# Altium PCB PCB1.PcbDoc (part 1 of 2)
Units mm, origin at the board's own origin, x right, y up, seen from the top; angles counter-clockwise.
Board outline 140.21 x 210.44 mm, 4 copper layers (Top Layer, Layer 1, Layer 2, Bottom Layer), stack 0.603 mm thick; 99 components, 45 nets, 371 pads, 603 vias.
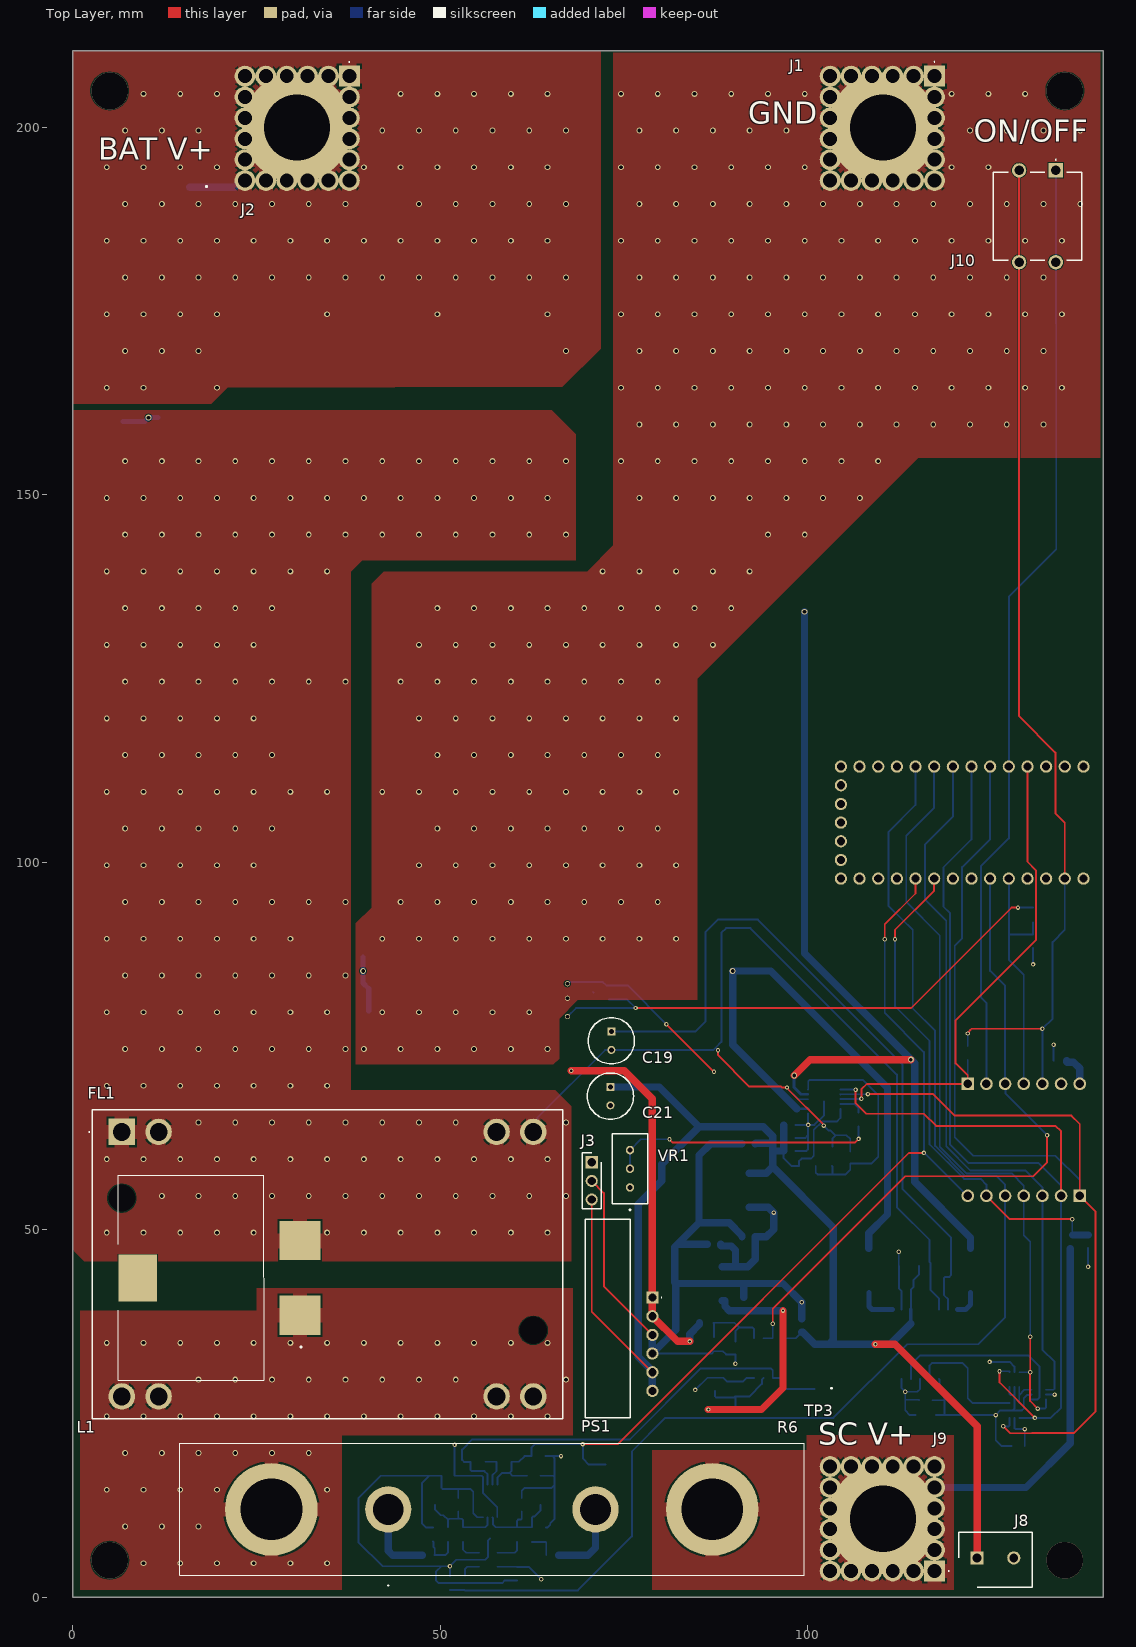
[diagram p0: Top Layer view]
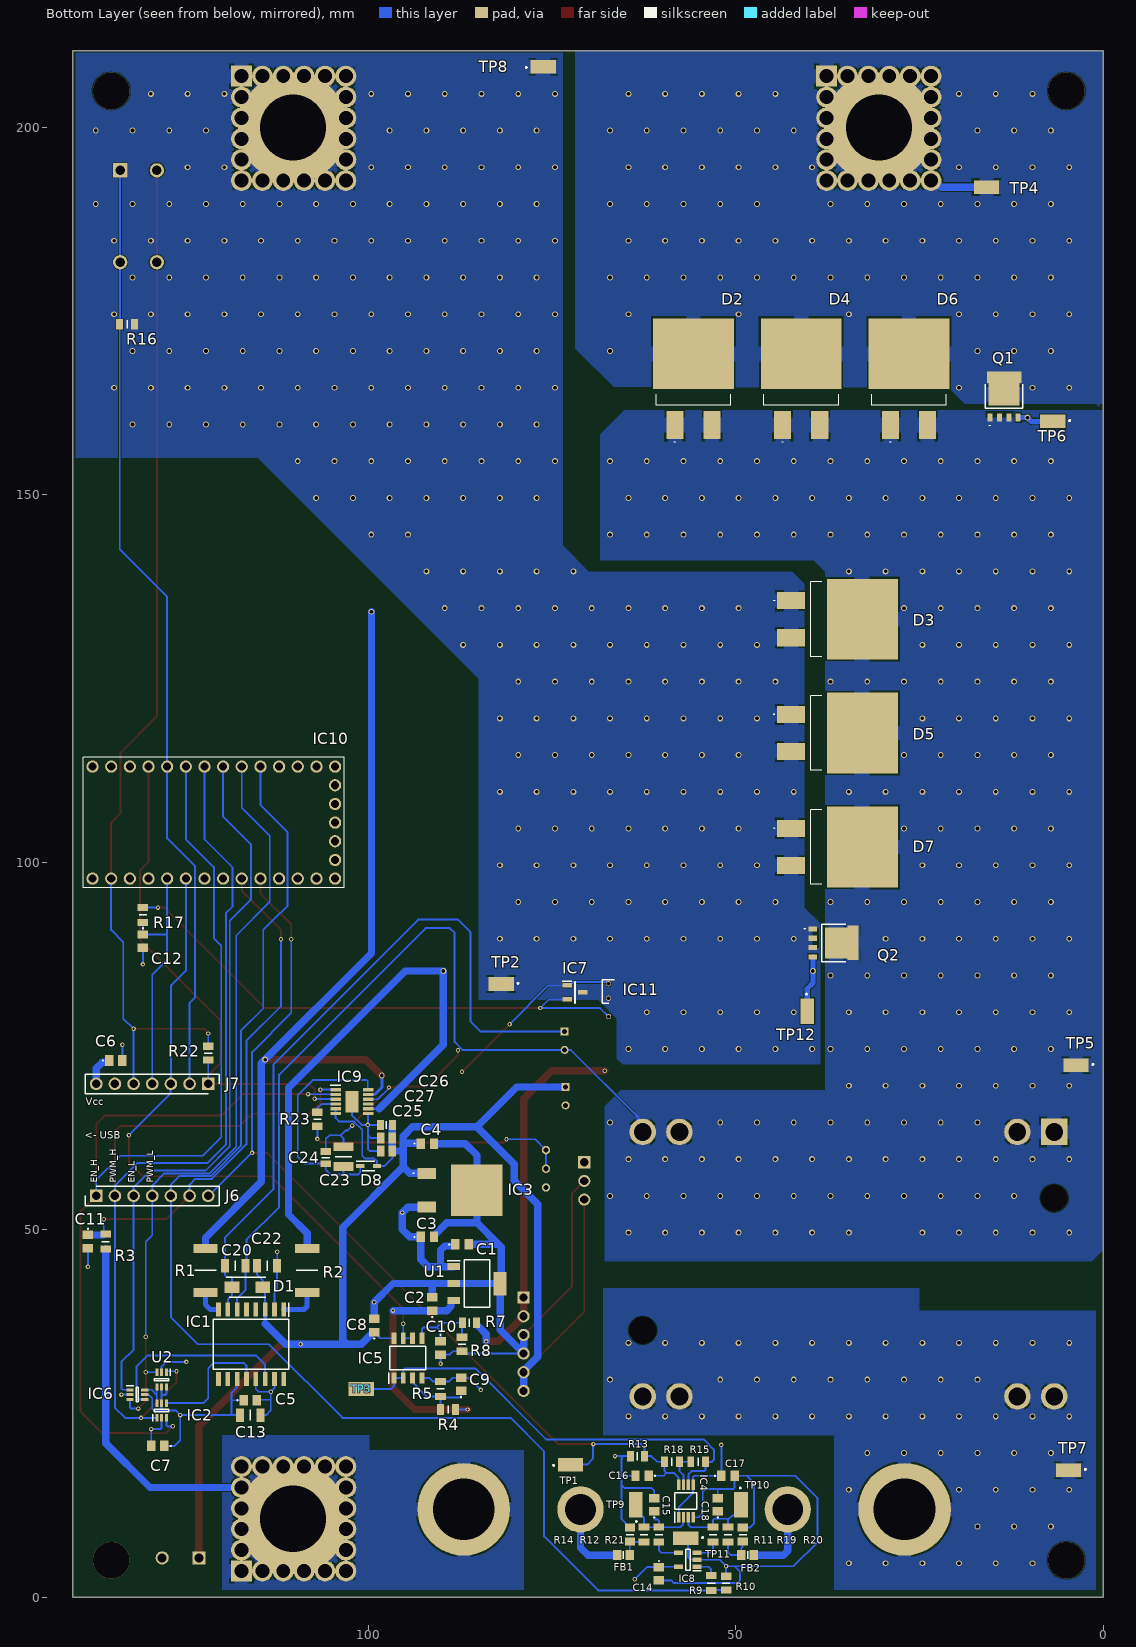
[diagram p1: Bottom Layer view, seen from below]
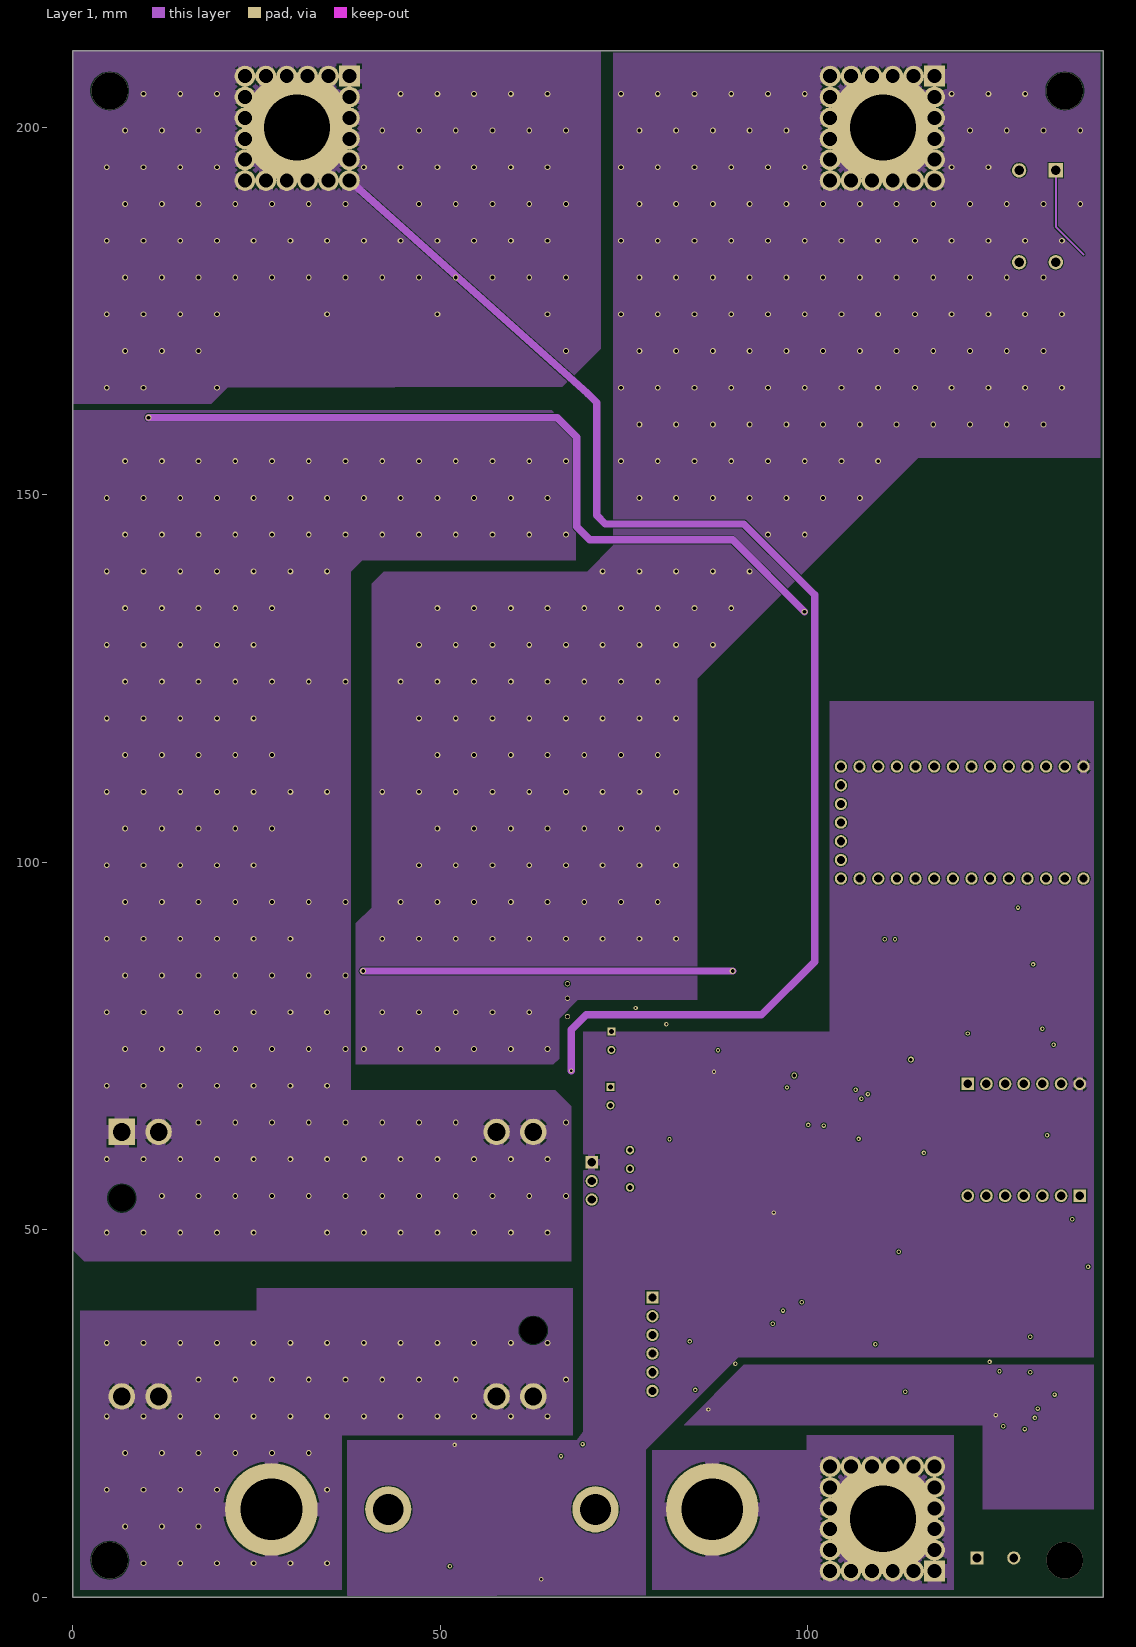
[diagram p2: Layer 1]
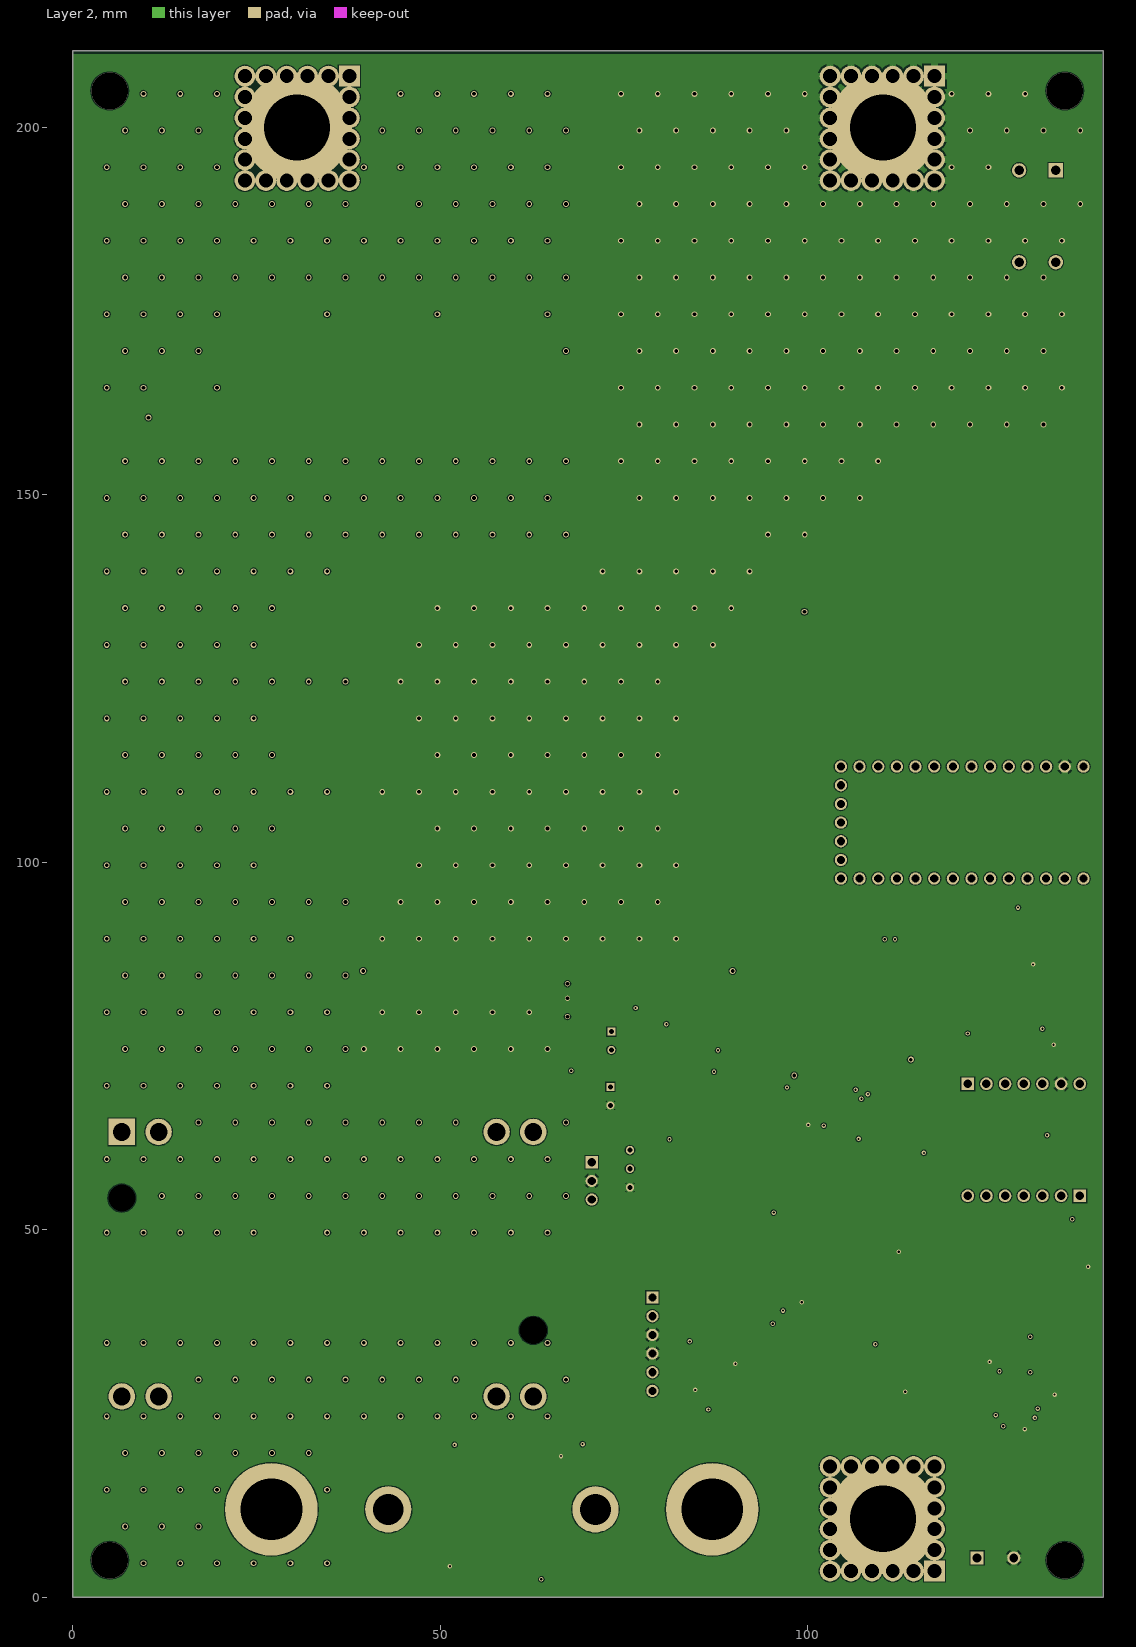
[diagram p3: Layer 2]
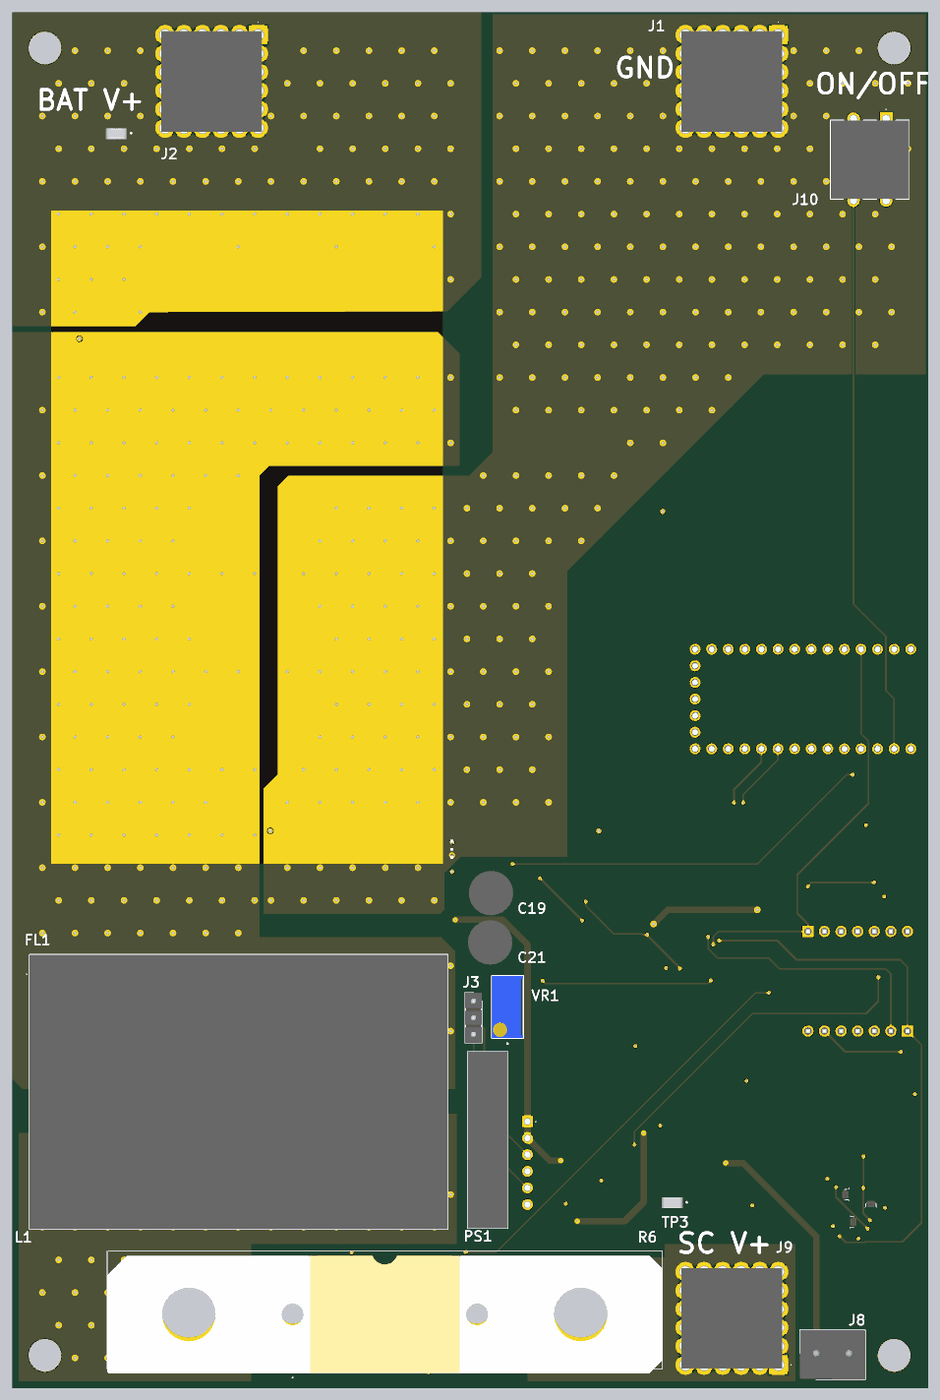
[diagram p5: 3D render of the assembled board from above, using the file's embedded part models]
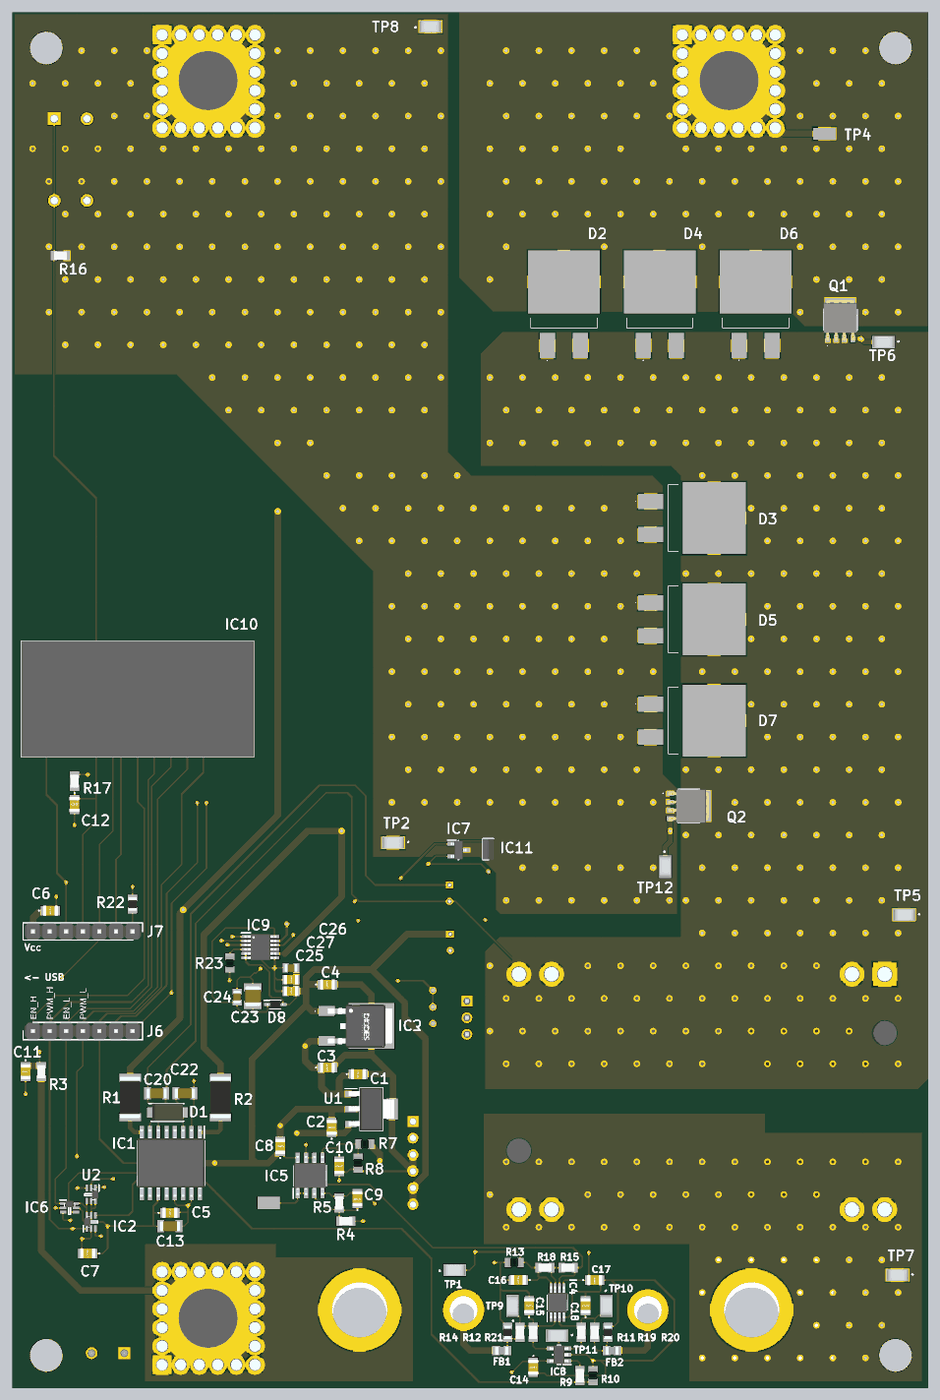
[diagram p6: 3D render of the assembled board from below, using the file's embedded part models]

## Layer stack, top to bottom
Top Solder: solder mask 0.0102, Solder Resist, Dk 3.5
Top Layer: signal copper 0.0356
Dielectric 2: prepreg 0.0711, PP-006, Dk 4.1
Layer 1: signal copper 0.035
Dielectric 1: dielectric 0.32, FR-4, Dk 4.8
Layer 2: signal copper 0.035
Dielectric 3: prepreg 0.0711, PP-006, Dk 4.1
Bottom Layer: signal copper 0.0356
Bottom Solder: solder mask 0.0102, Solder Resist, Dk 3.5

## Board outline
0,0 140.208,0 140.208,210.439 0,210.439

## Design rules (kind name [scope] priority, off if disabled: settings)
Clearance [All] p1: gap=0.127 ignorepadtopadclearanceinfootprint=FALSE
PolygonConnect PolygonConnect_5 [All vs IsNamedPolygon('GND') Or IsNamedPolygon('GND') Or IsNamedPolygon('GND') Or IsNamedPolygon('Top Layer-NetFL1_A2') Or IsNamedPolygon('Top Layer-SUPERCAPACITOR_V+') Or IsNamedPolygon('GND') Or IsNamedPolygon('GND') Or IsNamedPolygon('GND') Or IsNamedPolygon('Top Layer-NetFL1_A2') Or IsNamedPolygon('Top Layer-SUPERCAPACITOR_V+') Or IsNamedPolygon('GND') Or IsNamedPolygon('GND') Or IsNamedPolygon('Top Layer-NetFL1_A2') Or IsNamedPolygon('Top Layer-SUPERCAPACITOR_V+') Or IsNamedPolygon('GND') Or IsNamedPolygon('GND') Or IsNamedPolygon('GND') Or IsNamedPolygon('GND') Or IsNamedPolygon('Top Layer-NetFL1_A2') Or IsNamedPolygon('Top Layer-SUPERCAPACITOR_V+')] p1: thpad.connectstyle=Relief thpad.reliefconductorwidth=2 thpad.reliefentries=4 thpad.polygonreliefangle="90 Angle" thpad.airgapwidth=0.254 smdpad.connectstyle=Relief smdpad.reliefconductorwidth=2 smdpad.reliefentries=4 smdpad.polygonreliefangle="90 Angle" smdpad.airgapwidth=0.254 via.connectstyle=Direct via.reliefconductorwidth=0.254 via.reliefentries=4 via.polygonreliefangle="90 Angle" via.airgapwidth=0.254
PolygonConnect PolygonConnect_4 [All vs IsNamedPolygon('GND') Or IsNamedPolygon('GND') Or IsNamedPolygon('GND') Or IsNamedPolygon('Top Layer-NetFL1_A2') Or IsNamedPolygon('Top Layer-SUPERCAPACITOR_V+') Or IsNamedPolygon('GND') Or IsNamedPolygon('GND') Or IsNamedPolygon('GND') Or IsNamedPolygon('Layer 1-VCC_3V') Or IsNamedPolygon('Layer 1-VCC_5V') Or IsNamedPolygon('Top Layer-NetFL1_A2') Or IsNamedPolygon('Top Layer-SUPERCAPACITOR_V+') Or IsNamedPolygon('GND') Or IsNamedPolygon('GND') Or IsNamedPolygon('Layer 2-GND') Or IsNamedPolygon('Top Layer-NetFL1_A2') Or IsNamedPolygon('Top Layer-SUPERCAPACITOR_V+') Or IsNamedPolygon('GND') Or IsNamedPolygon('GND') Or IsNamedPolygon('GND') Or IsNamedPolygon('GND') Or IsNamedPolygon('Top Layer-NetFL1_A2') Or IsNamedPolygon('Top Layer-SUPERCAPACITOR_V+')] p2: thpad.connectstyle=Relief thpad.reliefconductorwidth=1 thpad.reliefentries=4 thpad.polygonreliefangle="90 Angle" thpad.airgapwidth=0.254 smdpad.connectstyle=Relief smdpad.reliefconductorwidth=1 smdpad.reliefentries=4 smdpad.polygonreliefangle="90 Angle" smdpad.airgapwidth=0.254 via.connectstyle=Direct via.reliefconductorwidth=0.254 via.reliefentries=4 via.polygonreliefangle="90 Angle" via.airgapwidth=0.254
PolygonConnect PolygonConnect_3 [All vs IsNamedPolygon('GND') Or IsNamedPolygon('GND') Or IsNamedPolygon('GND') Or IsNamedPolygon('Top Layer-NetFL1_A2') Or IsNamedPolygon('Top Layer-SUPERCAPACITOR_V+') Or IsNamedPolygon('GND') Or IsNamedPolygon('GND') Or IsNamedPolygon('GND') Or IsNamedPolygon('Layer 1-VCC_3V') Or IsNamedPolygon('Layer 1-VCC_5V') Or IsNamedPolygon('Top Layer-NetFL1_A2') Or IsNamedPolygon('Top Layer-SUPERCAPACITOR_V+') Or IsNamedPolygon('GND') Or IsNamedPolygon('GND') Or IsNamedPolygon('Layer 2-GND') Or IsNamedPolygon('Top Layer-NetFL1_A2') Or IsNamedPolygon('Top Layer-SUPERCAPACITOR_V+') Or IsNamedPolygon('GND') Or IsNamedPolygon('GND') Or IsNamedPolygon('GND') Or IsNamedPolygon('GND') Or IsNamedPolygon('Top Layer-NetFL1_A2') Or IsNamedPolygon('Top Layer-SUPERCAPACITOR_V+')] p3: thpad.connectstyle=Relief thpad.reliefconductorwidth=0.5 thpad.reliefentries=4 thpad.polygonreliefangle="90 Angle" thpad.airgapwidth=0.254 smdpad.connectstyle=Relief smdpad.reliefconductorwidth=0.254 smdpad.reliefentries=4 smdpad.polygonreliefangle="90 Angle" smdpad.airgapwidth=0.254 via.connectstyle=Relief via.reliefconductorwidth=0.254 via.reliefentries=4 via.polygonreliefangle="90 Angle" via.airgapwidth=0.254
PolygonConnect PolygonConnect_2 [All vs IsNamedPolygon('GND') Or IsNamedPolygon('GND') Or IsNamedPolygon('GND') Or IsNamedPolygon('Top Layer-NetFL1_A2') Or IsNamedPolygon('Top Layer-SUPERCAPACITOR_V+') Or IsNamedPolygon('GND') Or IsNamedPolygon('GND') Or IsNamedPolygon('GND') Or IsNamedPolygon('Layer 1-VCC_3V') Or IsNamedPolygon('Layer 1-VCC_5V') Or IsNamedPolygon('Top Layer-NetFL1_A2') Or IsNamedPolygon('Top Layer-SUPERCAPACITOR_V+') Or IsNamedPolygon('GND') Or IsNamedPolygon('GND') Or IsNamedPolygon('Layer 2-GND') Or IsNamedPolygon('Top Layer-NetFL1_A2') Or IsNamedPolygon('Top Layer-SUPERCAPACITOR_V+') Or IsNamedPolygon('GND') Or IsNamedPolygon('GND') Or IsNamedPolygon('GND') Or IsNamedPolygon('GND') Or IsNamedPolygon('Top Layer-NetFL1_A2') Or IsNamedPolygon('Top Layer-SUPERCAPACITOR_V+')] p4: thpad.connectstyle=Relief thpad.reliefconductorwidth=0.254 thpad.reliefentries=4 thpad.polygonreliefangle="90 Angle" thpad.airgapwidth=0.254 smdpad.connectstyle=Relief smdpad.reliefconductorwidth=0.254 smdpad.reliefentries=4 smdpad.polygonreliefangle="90 Angle" smdpad.airgapwidth=0.254 via.connectstyle=Direct via.reliefconductorwidth=0.254 via.reliefentries=4 via.polygonreliefangle="90 Angle" via.airgapwidth=0.254
PolygonConnect HESS2 [All vs IsNamedPolygon('GND') Or IsNamedPolygon('Top Layer-NetFL1_A2') Or IsNamedPolygon('Top Layer-SUPERCAPACITOR_V+') Or IsNamedPolygon('Top Layer-SUPERCAPACITOR_V+') Or IsNamedPolygon('GND') Or IsNamedPolygon('Top Layer-SUPERCAPACITOR_V+') Or IsNamedPolygon('GND') Or IsNamedPolygon('GND') Or IsNamedPolygon('GND') Or IsNamedPolygon('GND') Or IsNamedPolygon('Top Layer-SUPERCAPACITOR_V+')] p5: thpad.connectstyle=Relief thpad.reliefconductorwidth=1 thpad.reliefentries=4 thpad.polygonreliefangle="90 Angle" thpad.airgapwidth=0.254 smdpad.connectstyle=Relief smdpad.reliefconductorwidth=1 smdpad.reliefentries=4 smdpad.polygonreliefangle="90 Angle" smdpad.airgapwidth=0.254 via.connectstyle=Relief via.reliefconductorwidth=0.254 via.reliefentries=4 via.polygonreliefangle="90 Angle" via.airgapwidth=0.254
PolygonConnect PolygonConnect_1 [All vs IsNamedPolygon('GND')] p6: thpad.connectstyle=Relief thpad.reliefconductorwidth=1 thpad.reliefentries=4 thpad.polygonreliefangle="90 Angle" thpad.airgapwidth=0.254 smdpad.connectstyle=Relief smdpad.reliefconductorwidth=1 smdpad.reliefentries=4 smdpad.polygonreliefangle="90 Angle" smdpad.airgapwidth=0.254 via.connectstyle=Relief via.reliefconductorwidth=0.254 via.reliefentries=4 via.polygonreliefangle="90 Angle" via.airgapwidth=0.254
PolygonConnect HESS [All vs IsNamedPolygon('GND')] p7: thpad.connectstyle=Relief thpad.reliefconductorwidth=1 thpad.reliefentries=4 thpad.polygonreliefangle="90 Angle" thpad.airgapwidth=0.254 smdpad.connectstyle=Relief smdpad.reliefconductorwidth=0.254 smdpad.reliefentries=4 smdpad.polygonreliefangle="90 Angle" smdpad.airgapwidth=0.254 via.connectstyle=Relief via.reliefconductorwidth=0.254 via.reliefentries=4 via.polygonreliefangle="90 Angle" via.airgapwidth=0.254
PolygonConnect [All] p8: connectstyle=Relief reliefconductorwidth=0.254 reliefentries=4 polygonreliefangle="90 Angle" airgapwidth=0.254
RoutingVias [All] p1: holewidth=0.711 width=1.27 viastyle="Through Hole" minholewidth=0.711 minwidth=1.27 maxholewidth=0.711 maxwidth=1.27
SolderMaskExpansion [All] p1: expansion=0.102 istentingtop=FALSE
SupplyNets "Schematic Supply Nets" [InNet('GND')] p1: voltage=0.000
Width [All] p1: maxlimit=2.54 minlimit=0.254 preferedwidth=1
30 further rules are at their usual default settings.

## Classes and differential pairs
component class DRIVER_2: C23 C24 C25 C26 C27 D8 IC9 R22 R23 VR1
component class CURRENT_SENSE: C14 C15 C16 C17 C18 FB1 FB2 IC4 IC8 R9 R10 R11 R12 R13 R14 R15 R18 R19 R20 R21 TP1 TP3 TP9 TP10 TP11
component class MOSFET_AND_INTRUMENTAL_AMPLIFIERS: C8 C9 C10 D2 D3 D4 D5 D6 D7 FL1 IC5 J1 J2 J9 L1 Q1 Q2 R4 R5 R6 R7 R8 TP2 TP4 TP5 TP6 TP7 TP8 TP12
component class MCU: C11 C12 IC7 IC10 IC11 J6 J7 J10 R3 R16 R17
component class DRIVER_ADN_REGULATORS: C1 C2 C3 C4 C5 C6 C7 C13 C19 C20 C21 C22 D1 IC1 IC2 IC3 IC6 J3 J8 PS1 R1 R2 U1 U2

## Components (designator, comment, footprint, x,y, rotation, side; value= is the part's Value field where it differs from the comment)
C1 "0.33 uF" C0805 87.249,48.006 r180 bottom
C2 "0.1 uF" C0805 91.313,39.878 r90 bottom
C3 "0.1 uF" C0805 91.962,49.022 r180 bottom
C4 "0.33 uF" C0805 91.962,61.722 r180 bottom
C5 "0.1 uF" C0805 116.078,26.797 r180 bottom
C6 "0.1 uF" C0805 134.366,73.025 r180 bottom
C7 "0.1 uF" C0805 128.651,20.574 r0 bottom
C8 "0.1 uF" C0805 99.187,36.957 r90 bottom
C9 "0.1 uF" C0805 87.376,28.956 r90 bottom
C10 "0.1 uF" C0805 90.17,33.909 r270 bottom
C11 "0.1 uF" C0805 138.176,48.387 r270 bottom
C12 "0.1 uF" C0805 130.683,89.281 r270 bottom
C13 "10 uF" CAPC3216X180N 116.078,24.765 r180 bottom
C14 "0.1 uF" C0805 60.452,3.175 r270 bottom
C15 "0.1 uF" C0805 61.087,12.573 r90 bottom
C16 "0.1 uF" C0805 62.738,16.51 r0 bottom
C17 "0.1 uF" C0805 51.054,16.51 r180 bottom
C18 "0.1 uF" C0805 52.451,12.573 r90 bottom
C19 "100 uF" CAPPRD250W52D630H1250 73.279,76.962 r270 top
C20 "10 uF" CAPC3216X180N 118.11,45.085 r180 bottom
C21 "100 uF" CAPPRD250W52D630H1250 73.152,69.429 r270 top
C22 "10 uF" CAPC3216X180N 113.792,45.085 r180 bottom
C23 "22 uF" CAPC3225X270N 103.378,59.944 r270 bottom
C24 "1 uF" CAPC2012X135N 105.791,59.817 r270 bottom
C25 "0.1 uF" CAPC2012X88N 97.536,60.706 r0 bottom
C26 "1 uF" CAPC2012X135N 97.536,64.262 r0 bottom
C27 "0.22 uF" CAPC2012X140N 97.536,62.484 r0 bottom
D1 "SK34SMA-3G" DIOM5027X240N 116.459,42.164 r180 bottom
D2 "VS-42CTQ030S-M3" VS42CTQ030SM3 55.753,163.195 r180 bottom
D3 "VS-42CTQ030S-M3" VS42CTQ030SM3 38.791,133.096 r270 bottom
D4 "VS-42CTQ030S-M3" VS42CTQ030SM3 41.084,163.195 r180 bottom
D5 "VS-42CTQ030S-M3" VS42CTQ030SM3 38.791,117.602 r270 bottom
D6 "VS-42CTQ030S-M3" VS42CTQ030SM3 26.416,163.195 r180 bottom
D7 "VS-42CTQ030S-M3" VS42CTQ030SM3 38.791,102.108 r270 bottom
D8 "PMEG2020AEA-QX" SOD2512X110N 99.949,58.674 r180 bottom
FB1 "742792022" BEADC2012X110N 65.278,5.715 r180 bottom
FB2 "742792022" BEADC2012X110N 48.387,5.715 r0 bottom
FL1 "RT8522-63-0M5" RT8522630M5 6.658,63.305 r180 top locked
IC1 "IR2010SPBF" SOIC127P1032X265-16N 115.951,34.417 r270 bottom
IC2 "74LVC1G11DW-7" SOT65P210X110-6N 128.143,25.4 r90 bottom
IC3 "AS7805ADTR-G1" AS7805ADTRG1 87.517,55.372 r270 bottom
IC4 "AD8237ARMZ-R7" SOP65P490X110-8N 56.769,13.081 r90 bottom
IC5 "TLV9152IDR" SOIC127P600X175-8N 94.615,32.512 r90 bottom
IC6 "74LVC1G11DW-7" SOT65P210X110-6N 131.445,27.559 r180 bottom
IC7 "TMP235A4DBZR" SOT95P237X112-3N 71.882,82.296 r180 bottom
IC8 "LMV7219M5X_NOPB" SOT95P280X145-5N 56.515,5.08 r0 bottom
IC9 "LTC7060EMSE#PBF" SOP65P490X110-13N 102.235,67.437 r180 bottom
IC10 "3800" 3800 137.541,97.79 r180 bottom locked
IC11 "LMT87LPGM" TO127P162X315X490-3P 67.31,81.153 r90 bottom
J1 "S98979" S98979 117.263,207 r270 top locked
J2 "S98979" S98979 37.62,207 r270 top locked
J3 "M20-9990346" HDRV3W64P0X254_1X3_762X254X864P 70.612,59.182 r270 top
J6 "M20-9770746" HDRV7W66P0X254_1X7_1778X254X844P 137.033,54.61 r180 bottom locked
J7 "M20-9770746" HDRV7W66P0X254_1X7_1778X254X844P 121.793,69.85 r0 bottom locked
J8 "494-8906" SHDR2W100P0X500_1X2_1000X750X1000P 123.063,5.334 r0 top
J9 "S98979" S98979 117.263,3.556 r180 top locked
J10 "TS14-1212-100-BK-160-SCR-D" TS141212100BK160SCRD 133.778,194.183 r270 top
L1 "SER2915H-223KL" SER2915H223KL 18.542,43.434 r90 top
PS1 "mEZD41502A-B" mEZD41502AB 78.867,40.767 r270 top
Q1 "PSMN0R7-25YLDX" BUK7J1R440HX 13.462,163.449 r180 bottom
Q2 "PSMN0R7-25YLDX" BUK7J1R440HX 36.597,89.027 r270 bottom
R1 "22 Ohms" RESC6331X75N 122.174,44.45 r90 bottom
R2 "22 Ohms" RESC6331X75N 108.331,44.45 r90 bottom
R3 "1 k" RESC2012X50N 135.763,48.387 r90 bottom
R4 "1 k" RESC2012X50N 89.154,25.527 r0 bottom
R5 "1 k" RESC2012X50N 90.17,28.321 r90 bottom
R6 "WSBS8518L2500JKM4" WSBS8518L2500JKM4 42.92,11.938 r0 top locked
R7 "100 k" RESC2012X60N 86.233,37.338 r0 bottom
R8 "100 k" RESC2012X60N 87.249,34.417 r270 bottom
R9 "1 k" RESC2012X50N 53.34,1.905 r270 bottom
R10 "2 k" RESC2012X60N 51.308,1.905 r90 bottom
R11 "1 k" RESC2012X50N 53.086,8.509 r90 bottom
R12 "1 k" RESC2012X50N 62.484,8.509 r90 bottom
R13 "100 k" RESC2012X60N 63.373,19.177 r0 bottom
R14 "330 k" RESC2012X70N 64.389,8.509 r90 bottom
R15 "1 k" RESC2012X50N 55.118,18.415 r0 bottom
R16 "1 k" RESC2012X50N 132.842,173.228 r180 bottom
R17 "1 k" RESC2012X50N 130.683,92.837 r270 bottom
R18 "1 k" RESC2012X50N 58.674,18.415 r0 bottom
R19 "1 k" RESC2012X50N 51.054,8.509 r90 bottom
R20 "330 k" RESC2012X70N 49.022,8.509 r90 bottom
R21 "1 k" RESC2012X50N 60.452,8.509 r90 bottom
R22 "51 k" RESC2013X65N 121.793,74.041 r270 bottom
R23 "20 k" RESC2012X60N 106.934,65.024 r270 bottom
TP1 "S1751-46R" S175146R#1 72.477,18.034 r0 bottom
TP2 "S1751-46R" S175146R#1 81.915,83.439 r180 bottom
TP3 "S1751-46R" S175146R#2 100.965,28.321 r0 top
TP4 "S1751-46R" S175146R#2 15.875,191.897 r0 top
TP5 "S1751-46R" S175146R#1 3.683,72.39 r180 bottom
TP6 "S1751-46R" S175146R#1 6.858,160.02 r180 bottom
TP7 "S1751-46R" S175146R#1 4.699,17.272 r180 bottom
TP8 "S1751-46R" S175146R#1 76.2,208.28 r0 bottom
TP9 "S1751-46R" S175146R#1 63.627,12.573 r270 bottom
TP10 "S1751-46R" S175146R#1 49.276,12.573 r90 bottom
TP11 "S1751-46R" S175146R#1 56.809,8.001 r180 bottom
TP12 "S1751-46R" S175146R#1 40.259,79.756 r90 bottom
U1 "UA78M33CDCYR" SOT230P700X180-4N 85.217,42.672 r180 bottom
U2 "74LVC1G10DW-7" SOT65P210X110-6N 128.143,29.591 r270 bottom
VR1 "3296W-1-104LF" 3296W1503LF 75.819,55.753 r270 top

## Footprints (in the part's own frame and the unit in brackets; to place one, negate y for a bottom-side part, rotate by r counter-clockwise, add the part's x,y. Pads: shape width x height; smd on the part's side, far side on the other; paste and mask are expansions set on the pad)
3296W1503LF [mm]
  round 1.15 hole 0.71: 1(0,0) 2(-2.54,0) 3(-5.08,0)
  silkscreen extent -7.3,-2.42 3.15,2.41, body extent -7.3,-2.41 2.22,2.41, height 11.54
3800 [mm]
  round 1.665 hole 1.11: 1(0,0) 2(2.54,0) 3(5.08,0) 4(7.62,0) 5(10.16,0) 6(12.7,0) 7(15.24,0) 8(17.78,0) 9(20.32,0) 10(22.86,0) 11(25.4,0) 12(27.94,0) 13(30.48,0) 14(33.02,0) 15(33.02,2.54) 16(33.02,5.08) 17(33.02,7.62) 18(33.02,10.16) 19(33.02,12.7) 20(33.02,15.24) 21(30.48,15.24) 22(27.94,15.24) 23(25.4,15.24) 24(22.86,15.24) 25(20.32,15.24) 26(17.78,15.24) 27(15.24,15.24) 28(12.7,15.24) 29(10.16,15.24) 30(7.62,15.24) 31(5.08,15.24) 32(2.54,15.24) 33(0,15.24)
  silkscreen extent -1.27,-1.27 34.29,16.51, body extent -1.27,-1.27 34.29,16.51, height 4.3
AS7805ADTRG1 [mm]
  rect 1.5x2.5 smd: 1(-2.3,-4.55) 3(2.3,-4.55)
  rect 7x7 smd: 2(0,2.3)
  silkscreen extent -2.35,-6.38 -2.25,-6.28, body extent -3.29,-4.41 3.29,5.5, height 2.48
BEADC2012X110N [mm]
  rect 1.2x1.4 smd: 1(-0.85,0) 2(0.85,0)
  silkscreen extent 0,-0.5 0,0.5, body extent -1,-0.6 1,0.6, height 1.1
BUK7J1R440HX [mm]
  rect 0.7x1.15 smd: 1(-1.905,-2.9) 2(-0.635,-2.9) 3(0.635,-2.9) 4(1.905,-2.9)
  rect 4.7x1.5 smd: 5(0,2.575)
  rect 4.2x3.1 smd: 6(0,0.275)
  silkscreen extent -2.56,-4.05 2.56,1.6, body extent -2.55,-3.14 2.55,3, height 1.04
C0805 [mm]
  rect 1.15x1.45 smd: 1(-0.9,0) 2(0.9,0)
  silkscreen extent -1.8,-0.05 -1.7,0.05, body extent -1.15,-0.78 1.15,0.77, height 0.98
CAPC2012X88N [mm]
  rect 1.02x1.47 smd: 1(-0.8,0) 2(0.8,0)
  body extent -1.1,-0.73 1.1,0.72, height 0.88
CAPC2012X135N [mm]
  rect 0.91x1.39 smd: 1(-0.82,0) 2(0.82,0)
  silkscreen extent 0,-0.53 0,0.53, body extent -1,-0.63 1,0.63, height 1.35
CAPC2012X140N [mm]
  rect 1.02x1.47 smd: 1(-0.8,0) 2(0.8,0)
  body extent -1.1,-0.73 1.1,0.72, height 1.4
CAPC3216X180N [mm]
  rect 1.07x1.82 smd: 1(-1.38,0) 2(1.38,0)
  silkscreen extent 0,-0.7 0,0.7, body extent -1.6,-0.8 1.6,0.8, height 1.8
CAPC3225X270N [mm]
  rect 1.22x2.72 smd: 1(-1.35,0) 2(1.35,0)
  silkscreen extent 0,-1.15 0,1.15, body extent -1.6,-1.25 1.6,1.25, height 2.7
CAPPRD250W52D630H1250 [mm]
  rect 1.1x1.1 hole 0.7: 1(0,0)
  round 1.1 hole 0.7: 2(2.5,0)
  silkscreen extent -1.9,-3.15 4.4,3.15, body extent -2.14,-3.4 4.65,3.4, height 12.5
DIOM5027X240N [mm]
  rect 2x1.55 smd: 1(-2.1,0) 2(2.1,0)
  silkscreen extent -2.88,-1.35 2.5,1.35, body extent -2.5,-1.35 2.5,1.35, height 2.4
HDRV3W64P0X254_1X3_762X254X864P [mm]
  rect 1.65x1.65 hole 1.1: 1(0,0)
  round 1.65 hole 1.1: 2(2.54,0) 3(5.08,0)
  silkscreen extent -1.27,-1.27 6.35,1.27, body extent -1.27,-1.27 6.35,1.27, height 8.64
HDRV7W66P0X254_1X7_1778X254X844P [mm]
  rect 1.725x1.725 hole 1.15: 1(0,0)
  round 1.725 hole 1.15: 2(2.54,0) 3(5.08,0) 4(7.62,0) 5(10.16,0) 6(12.7,0) 7(15.24,0)
  silkscreen extent -1.52,-1.32 16.76,1.32, body extent -1.27,-1.27 16.51,1.27, height 8.34
mEZD41502AB [mm]
  rect 1.665x1.665 hole 1.11: 1(0,0)
  round 1.665 hole 1.11: 2(2.54,0) 3(5.08,0) 4(7.62,0) 5(10.16,0) 6(12.7,0)
  silkscreen extent -10.65,-9.15 16.35,1.3, body extent -10.65,-9.15 16.35,0.45, height 20.1
RESC2012X50N [mm]
  rect 0.95x1.45 smd: 1(-1,0) 2(1,0)
  silkscreen extent 0,-0.53 0,0.53, body extent -1,-0.62 1,0.63, height 0.45
RESC2012X60N [mm]
  rect 1x1.45 smd: 1(-0.95,0) 2(0.95,0)
  silkscreen extent 0,-0.53 0,0.53, body extent -1,-0.63 1,0.63, height 0.5
RESC2012X70N [mm]
  rect 1.05x1.4 smd: 1(-0.95,0) 2(0.95,0)
  silkscreen extent 0,-0.53 0,0.53, body extent -1,-0.63 1,0.63, height 0.6
RESC2013X65N [mm]
  rect 1x1.45 smd: 1(-0.95,0) 2(0.95,0)
  silkscreen extent 0,-0.54 0,0.54, body extent -1,-0.64 1,0.64, height 0.65
RESC6331X75N [mm]
  rect 1.25x3.3 smd: 1(-3,0) 2(3,0)
  silkscreen extent 0,-1.45 0,1.45, body extent -3.15,-1.55 3.15,1.55, height 0.75
RT8522630M5 [mm]
  round 1.85 hole 3.7 unplated: 1(0,9) 2(-56,27)
  rect 3.6x3.6 hole 2.4: A1(0,0)
  round 3.6 hole 2.4: A2(0,36) A3(-51,0) A4(-51,36) B1(-5,0) B2(-5,36) B3(-56,0) B4(-56,36)
  silkscreen extent -60,-3 4.5,39, body extent -60,-3 4,39, height 64.1
S98979 [mm]
  rect 2.85x2.85 hole 1.9: 1(0,0)
  round 2.85 hole 1.9: 2(0,-2.84) 3(0,-5.68) 4(0,-8.52) 5(0,-11.36) 6(0,-14.2) 7(2.84,-14.2) 8(5.68,-14.2) 9(8.52,-14.2) 10(11.36,-14.2) 11(14.2,-14.2) 12(14.2,-11.36) 13(14.2,-8.52) 14(14.2,-5.68) 15(14.2,-2.84) 16(14.2,0) 17(11.36,0) 18(8.52,0) 19(5.68,0) 20(2.84,0)
  silkscreen extent -2,-0.05 -1.9,0.05, body extent -0.85,-15.04 15.05,0.84, height 26.2
S175146R#1 [mm]
  rect 3.45x1.85 smd: 1(0,0)
  silkscreen extent 2.2,0 2.4,0.2, body extent -1.58,-0.83 1.67,0.82, height 2.05
S175146R#2 [mm]
  rect 3.45x1.85 smd far side: 1(0,0)
  silkscreen extent 2.2,0 2.4,0.2, body extent -1.58,-0.83 1.67,0.82, height 2.05
SER2915H223KL [mm]
  rect 5.33x5.59 smd: 1(-5.075,-12.357) 2(5.075,-12.357)
  rect 6.35x5.28 smd: 3(0,9.718)
  silkscreen extent -13.92,-12.6 13.95,12.36, body extent -14.07,-14.72 13.83,12.32, height 15.35
SHDR2W100P0X500_1X2_1000X750X1000P [mm]
  rect 1.8x1.8 hole 1.2: 1(0,0)
  round 1.8 hole 1.2: 2(5,0)
  silkscreen extent -2.5,-4 7.5,3.5, body extent -2.5,-4 7.5,3.5, height 10
SOD2512X110N [mm]
  rect 1.1x0.5 smd: 1(-1.15,0) 2(1.15,0)
  silkscreen extent -1.7,-0.63 0.85,0.63, body extent -1.24,-0.62 1.24,0.63, height 0.93
SOIC127P600X175-8N [mm]
  rect 1.525x0.65 smd: 1(-2.712,1.905) 2(-2.712,0.635) 3(-2.712,-0.635) 4(-2.712,-1.905) 5(2.712,-1.905) 6(2.712,-0.635) 7(2.712,0.635) 8(2.712,1.905)
  silkscreen extent -3.47,-2.45 1.6,2.58, body extent -3,-2.45 3,2.45, height 1.75
SOIC127P1032X265-16N [mm]
  rect 1.925x0.65 smd: 1(-4.712,4.445) 2(-4.712,3.175) 3(-4.712,1.905) 4(-4.712,0.635) 5(-4.712,-0.635) 6(-4.712,-1.905) 7(-4.712,-3.175) 8(-4.712,-4.445) 9(4.712,-4.445) 10(4.712,-3.175) 11(4.712,-1.905) 12(4.712,-0.635) 13(4.712,0.635) 14(4.712,1.905) 15(4.712,3.175) 16(4.712,4.445)
  silkscreen extent -5.68,-5.15 3.4,5.15, body extent -5.16,-5.15 5.16,5.15, height 2.65
SOP65P490X110-8N [mm]
  rect 1.45x0.45 smd: 1(-2.225,0.975) 2(-2.225,0.325) 3(-2.225,-0.325) 4(-2.225,-0.975) 5(2.225,-0.975) 6(2.225,-0.325) 7(2.225,0.325) 8(2.225,0.975)
  silkscreen extent -2.95,-1.5 1.15,1.55, body extent -2.45,-1.5 2.45,1.5, height 1.1
SOP65P490X110-13N [mm]
  rect 1.425x0.45 smd: 1(-2.212,1.625) 2(-2.212,0.975) 3(-2.212,0.325) 4(-2.212,-0.325) 5(-2.212,-0.975) 6(-2.212,-1.625) 7(2.212,-1.625) 8(2.212,-0.975) 9(2.212,-0.325) 10(2.212,0.325) 11(2.212,0.975) 12(2.212,1.625)
  rect 1.753x2.947 smd: 13(0,0)
  silkscreen extent -2.93,2.2 -1.5,2.2, body extent -2.45,-2.01 2.45,2.03, height 1.1
SOT65P210X110-6N [mm]
  rect 1x0.4 smd: 1(-1,0.65) 2(-1,0) 3(-1,-0.65) 4(1,-0.65) 5(1,0) 6(1,0.65)
  silkscreen extent -1.5,-1 0.15,1.2, body extent -1.05,0 1.05,1.1, height 1.07
SOT95P237X112-3N [mm]
  rect 1.3x0.6 smd: 1(-1.05,0.95) 2(-1.05,-0.95) 3(1.05,0)
  silkscreen extent -1.7,-1.46 0.05,1.5, body extent -1.18,-1.46 1.19,1.46, height 1.12
SOT95P280X145-5N [mm]
  rect 1.2x0.6 smd: 1(-1.25,0.95) 2(-1.25,0) 3(-1.25,-0.95) 4(1.25,-0.95) 5(1.25,0.95)
  silkscreen extent -1.85,-1.45 0.3,1.5, body extent -1.4,-1.45 1.4,1.45, height 1.2
SOT230P700X180-4N [mm]
  rect 1.75x0.95 smd: 1(-3.15,2.3) 2(-3.15,0) 3(-3.15,-2.3)
  rect 1.75x3.2 smd: 4(3.15,0)
  silkscreen extent -4.03,-3.25 1.75,3.25, body extent -3.5,-3.25 3.5,3.25, height 1.68
TO127P162X315X490-3P [mm]
  round 0.7 hole 0.5: 1(-2.153,0) 2(0.347,0) 3(2.327,0)
  silkscreen extent -0.36,-0.76 2.9,0.86, body extent -0.31,-0.76 2.85,0.86, height 4.9
TS141212100BK160SCRD [mm]
  rect 1.95x1.95 hole 1.3: 1(0,0)
  round 1.95 hole 1.3: 2(12.5,0) 3(0,-5) 4(12.5,-5)
  silkscreen extent -1.5,-8.5 12.25,3.5, body extent -0.55,-8.5 13.05,3.5, height 10.3
VS42CTQ030SM3 [mm]
  rect 2.32x3.81 smd: 1(-2.525,-3.695) 3(2.525,-3.695)
  rect 11x9.65 smd: 2(0,6.025)
  silkscreen extent -5.08,-6.02 5.08,0.5
WSBS8518L2500JKM4 [mm]
  round 6.3 hole 4.2: 1(0,0) 2(28.2,0)
  round 12.6 hole 8.4: MH1(-15.9,0) MH2(44.1,0)
  silkscreen extent -28.4,-10.4 56.6,9, body extent -28.39,-9.69 56.6,8.29, height 3

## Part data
C1 C4: library part C0805C334K5RACAUTO, "Capacitor", Manufacturer_Name=KEMET, Mouser Part Number=80-C0805C334K5RAUTO
C2 C3 C5 C6 C7 C8 C9 C10 C11 C12 C14 C15 C16 C17 C18: library part C0805C104M5RACTU, "Capacitor", Manufacturer_Name=KEMET, Mouser Part Number=80-C0805C104M5R
C13 C20 C22: library part CL31B106KAHNNNE, "Capacitor", Manufacturer_Name=SAMSUNG, Mouser Part Number=187-CL31B106KAHNNNE
C19 C21: library part 860010473007, "Capacitor Polarised", Manufacturer_Name="Wurth Elektronik", Mouser Part Number=710-860010473007
C23: library part CL32B226KAJNNNE, "Capacitor", Manufacturer_Name=SAMSUNG, Mouser Part Number=187-CL32B226KAJNNNE
C24 C26: library part CL21B105MBFNNNE, "Capacitor", Manufacturer_Name=SAMSUNG, Mouser Part Number=187-CL21B105MBFNNNE
C25: library part C0805C104M5RAC, "Capacitor", Manufacturer_Name=KEMET, Mouser Part Number=80-C0805C104M5RAC
C27: library part C0805C224K5RAC7800, "Capacitor", Manufacturer_Name=KEMET, Mouser Part Number=80-C0805C224K5R7800
D1: "Schottky Diode", Manufacturer_Name=Diotec, Mouser Part Number=637-SK34SMA-3G
D2 D3 D4 D5 D6 D7: "Schottky Diode", Manufacturer_Name=Vishay, Mouser Part Number=78-VS-42CTQ030S-M3
D8: "Schottky Diode", Manufacturer_Name=Nexperia, Mouser Part Number=771-PMEG2020AEA-QX
FB1 FB2: "Ferrite Bead", Manufacturer_Name="Wurth Elektronik", Mouser Part Number=710-742792022
FL1: "Filter", Manufacturer_Name=Schaffner, Mouser Part Number=631-RT8522-63-0M5
IC1: "Integrated Circuit", Manufacturer_Name=Infineon, Mouser Part Number=942-IR2010SPBF
IC2 IC6: "Integrated Circuit", Manufacturer_Name="Diodes Incorporated", Mouser Part Number=621-74LVC1G11DW-7
IC3: "Integrated Circuit", Manufacturer_Name="Diodes Incorporated", Mouser Part Number=621-AS7805ADTR-G1
IC4: "Integrated Circuit", Manufacturer_Name="Analog Devices", Mouser Part Number=584-AD8237ARMZ-R7
IC5: "Integrated Circuit", Manufacturer_Name="Texas Instruments", Mouser Part Number=595-TLV9152IDR
IC7: "Integrated Circuit", Manufacturer_Name="Texas Instruments", Mouser Part Number=595-TMP235A4DBZR
IC8: "Integrated Circuit", Arrow Part Number=LMV7219M5X/NOPB, Manufacturer_Name="Texas Instruments", Mouser Part Number=926-LMV7219M5X/NOPB
IC9: "Integrated Circuit", Manufacturer_Name="Analog Devices", Mouser Part Number=584-LTC7060EMSEPBF
IC10: "Integrated Circuit", Manufacturer_Name=Adafruit, Mouser Part Number=485-3800
IC11: "Integrated Circuit", Manufacturer_Name="Texas Instruments", Mouser Part Number=595-LMT87LPGM
J1 J2 J9: "Connector", Manufacturer_Name="Wurth Elektronik"
J3: "Connector", Manufacturer_Name=Harwin, Mouser Part Number=855-M20-9990346
J6 J7: "Connector", Manufacturer_Name=Harwin, Mouser Part Number=855-M20-9770746
J8: "Connector", Manufacturer_Name="RS Pro"
J10: "Connector", Manufacturer_Name="Same Sky", Mouser Part Number=179-TS141212100160SC
L1: "Inductor", Manufacturer_Name=COILCRAFT, Mouser Part Number=994-SER2915H-223KL
PS1: "Power Supply", Manufacturer_Name="Monolithic Power Systems (MPS)", Mouser Part Number=946-MEZD41502A-B
Q1 Q2: "MOSFET (N-Channel)", Manufacturer_Name=Nexperia, Mouser Part Number=771-PSMN0R7-25YLDX
R1 R2: library part CR2512-JW-220ELF, "Resistor", Manufacturer_Name=Bourns, Mouser Part Number=652-CR2512-JW-220ELF
R3 R4 R5 R9 R11 R12 R15 R16 R17 R18 R19 R21: library part CRCW08051K00FKEA, "Resistor", Manufacturer_Name=Vishay, Mouser Part Number=71-CRCW0805-1.0K-E3
R6: "Resistor", Manufacturer_Name=Vishay, Mouser Part Number=71-WSBS8518L2500JKM4
R7 R8 R13: library part CR0805-FX-1003ELF, "Resistor", Manufacturer_Name=Bourns, Mouser Part Number=652-CR0805FX-1003ELF
R10: library part CR0805-JW-202ELF, "Resistor", Manufacturer_Name=Bourns, Mouser Part Number=652-CR0805JW-202ELF
R14 R20: library part ERJ-6GEYJ334V, "Resistor", Manufacturer_Name=Panasonic, Mouser Part Number=667-ERJ-6GEYJ334V
R22: library part 0805W8F5102T5E, "Resistor", Manufacturer_Name="UNI-ROYAL(Uniroyal Elec)"
R23: library part CR0805-FX-2002ELF, "Resistor", Manufacturer_Name=Bourns, Mouser Part Number=652-CR0805FX-2002ELF
TP1 TP2 TP3 TP4 TP5 TP6 TP7 TP8 TP9 TP10 TP11 TP12: "Test Point", Manufacturer_Name=Harwin, Mouser Part Number=855-S1751-46R
U1: "Undefined or Miscellaneous", Manufacturer_Name="Texas Instruments", Mouser Part Number=595-UA78M33CDCYR
U2: "Undefined or Miscellaneous", Manufacturer_Name="Diodes Incorporated", Mouser Part Number=621-74LVC1G10DW-7
VR1: "Variable Resistor", Manufacturer_Name=Bourns, Mouser Part Number=652-3296W-1-104LF

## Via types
v1: diameter 0.8/0.8/0.8/0.8 (per signal layer), hole 0.5, Top Layer to Bottom Layer, 546 vias
v2: diameter 0.6, hole 0.3, Top Layer to Bottom Layer, 50 vias
v3: diameter 5, hole 5, Top Layer to Bottom Layer, 4 vias
v4: diameter 15, hole 9, Top Layer to Bottom Layer, 3 vias

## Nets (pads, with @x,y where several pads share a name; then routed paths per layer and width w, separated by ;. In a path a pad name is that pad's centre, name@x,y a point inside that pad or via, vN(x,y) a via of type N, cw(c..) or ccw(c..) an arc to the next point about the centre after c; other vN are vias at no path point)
AD8237_VOUT: C16.1 IC4.8 IC10.10 J6.7 R13.1 R18.2 TP1.1 | length 136.4
  Top Layer w0.254: v2(69.369,20.828) 74.168,20.828 113.792,60.452 v2(115.824,60.452) ; v2(110.49,89.535) 110.49,91.567 114.681,95.758 IC10.10@114.681,97.79
  Bottom Layer w0.254: IC4.8@57.744,15.306 57.78,15.342 57.78,16.251 58.42,16.891 59.436,16.891 ; C16.1@61.838,16.51 59.817,16.51 59.436,16.891 ; TP1.1@72.477,18.034 70.231,18.034 69.435,18.83 69.435,20.762 v2(69.369,20.828) 62.865,20.828 62.423,20.386 R13.1@62.423,19.177 61.468,19.177 60.706,18.415 R18.2@59.674,18.415 59.674,17.129 59.436,16.891 ; v2(110.49,89.535) 110.49,79.502 115.824,74.168 v2(115.824,60.452) 115.888,60.452 121.73,54.61 J6.7@121.793,54.61
BATTERY_SENSE: IC5.6 IC5.7 IC10.6 J7.3 | length 92.7
  Top Layer w0.254: v2(95.25,37.211) 95.25,39.243 113.284,57.277 130.683,57.277 132.588,59.182 v2(132.588,62.865)
  Bottom Layer w0.254: IC5.6@93.98,35.224 IC5.7@95.25,35.224 v2(95.25,37.211) ; IC10.6@124.841,97.79 124.841,85.217 126.873,83.185 J7.3@126.873,69.85 126.94,69.783 126.94,68.513 v2(132.588,62.865)
BATTERY_V+: D2.2 D4.2 D6.2 J2.1 J2.2 J2.3 J2.4 J2.5 J2.6 J2.7 J2.8 J2.9 J2.10 J2.11 J2.12 J2.13 J2.14 J2.15 J2.16 J2.17 J2.18 J2.19 J2.20 PS1.1 PS1.2 Q1.5 Q1.6 R7.1 TP4.1 | length 247
  Top Layer w1: v2(67.818,71.628) 75.057,71.628 78.867,67.818 PS1.1@78.867,40.767 PS1.2@78.867,38.227 82.296,34.798 v2(83.947,34.798)
  Layer 1 w1: J2.16@37.62,192.8 70.078,163.792 70.119,163.754 71.28,162.593 71.28,147.23 72.46,146.05 91.313,146.05 100.965,136.398 100.965,86.487 93.726,79.248 69.85,79.248 67.818,77.216 v2(67.818,71.628)
  Bottom Layer w1: TP4.1@15.875,191.897 22.016,191.897 22.919,192.8 J2.11@23.42,192.8 ; v2(83.947,34.798) 83.947,35.777 85.283,37.113 R7.1@85.283,37.338
  other v1: 4.6,164.6 9.6,164.6 19.6,164.6 7.1,169.6 12.1,169.6 17.1,169.6 67.1,169.6 4.6,174.6 9.6,174.6 14.6,174.6 19.6,174.6 34.6,174.6 49.6,174.6 64.6,174.6 7.1,179.6 12.1,179.6 17.1,179.6 22.1,179.6 27.1,179.6 32.1,179.6 37.1,179.6 42.1,179.6 47.1,179.6 52.1,179.6 57.1,179.6 62.1,179.6 67.1,179.6 4.6,184.6 9.6,184.6 14.6,184.6 19.6,184.6 24.6,184.6 29.6,184.6 34.6,184.6 39.6,184.6 44.6,184.6 49.6,184.6 54.6,184.6 59.6,184.6 64.6,184.6 7.1,189.6 12.1,189.6 17.1,189.6 22.1,189.6 27.1,189.6 32.1,189.6 37.1,189.6 47.1,189.6 52.1,189.6 57.1,189.6 62.1,189.6 67.1,189.6 4.6,194.6 9.6,194.6 14.6,194.6 19.6,194.6 39.6,194.6 44.6,194.6 49.6,194.6 54.6,194.6 59.6,194.6 64.6,194.6 7.1,199.6 12.1,199.6 17.1,199.6 42.1,199.6 47.1,199.6 52.1,199.6 57.1,199.6 62.1,199.6 67.1,199.6 9.6,204.6 14.6,204.6 19.6,204.6 44.6,204.6 49.6,204.6 54.6,204.6 59.6,204.6 64.6,204.6
  other v4: 30.48,200.025
BOT: IC10.29 J7.2 J10.1 J10.2 R16.1 | length 141.9
  Layer 1 w0.254: J10.1@133.778,194.183 133.778,186.516 137.541,182.753
  Bottom Layer w0.254: J7.2@124.333,69.85 124.333,80.899 123.571,81.661 123.571,99.441 127.381,103.251 127.381,136.176 133.842,142.637 R16.1@133.842,173.228 133.778,173.292 J10.2@133.778,181.683 J10.1@133.778,194.183
COMPARATOR_OUT: IC10.24 J6.5 R9.2 R10.1 | length 183.3
  Bottom Layer w0.254: R10.1@51.308,0.955 53.29,0.955 R9.2@53.34,0.905 68.723,0.905 76.073,8.255 76.073,19.812 80.645,24.384 103.505,24.384 113.538,34.417 123.19,34.417 126.873,38.1 J6.5@126.873,54.61 126.873,56.134 125.721,57.286 121.459,57.286 117.348,61.397 117.348,77.058 114.3,80.106 114.3,90.805 112.843,92.262 110.983,94.122 110.983,104.125 114.681,107.823 IC10.24@114.681,113.03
